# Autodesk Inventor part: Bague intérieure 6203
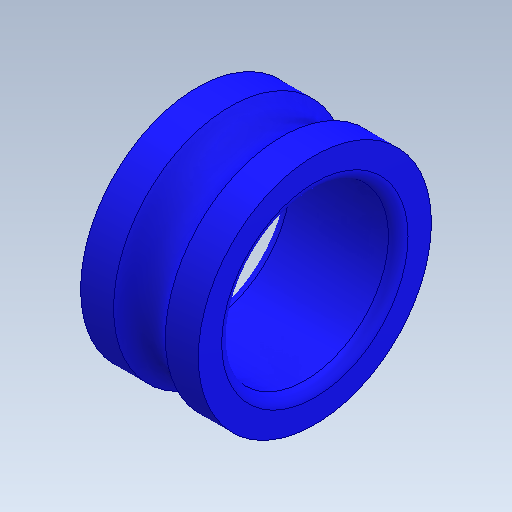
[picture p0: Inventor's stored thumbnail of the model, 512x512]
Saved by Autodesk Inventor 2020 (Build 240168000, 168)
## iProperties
Created: 2003-06
Part Number: Bague intérieure 6203
Material: Générique
Document SubType Name: Modeling
Designer: Bruno
Density: 1 g/cm^3
Appearance: Par défaut
Author: Bruno
Sending System: SolidWorks 2011
Last Author: frederic
Last Saved: 2012-02-20
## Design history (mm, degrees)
feature "Base-Révolution"
node "Solide1"
